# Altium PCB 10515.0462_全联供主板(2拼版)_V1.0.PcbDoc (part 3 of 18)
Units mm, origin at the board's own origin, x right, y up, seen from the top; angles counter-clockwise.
Board outline 282 x 198 mm, 2 copper layers (Top Layer, Bottom Layer); 716 components, 0 nets, 2364 pads, 1800 vias.
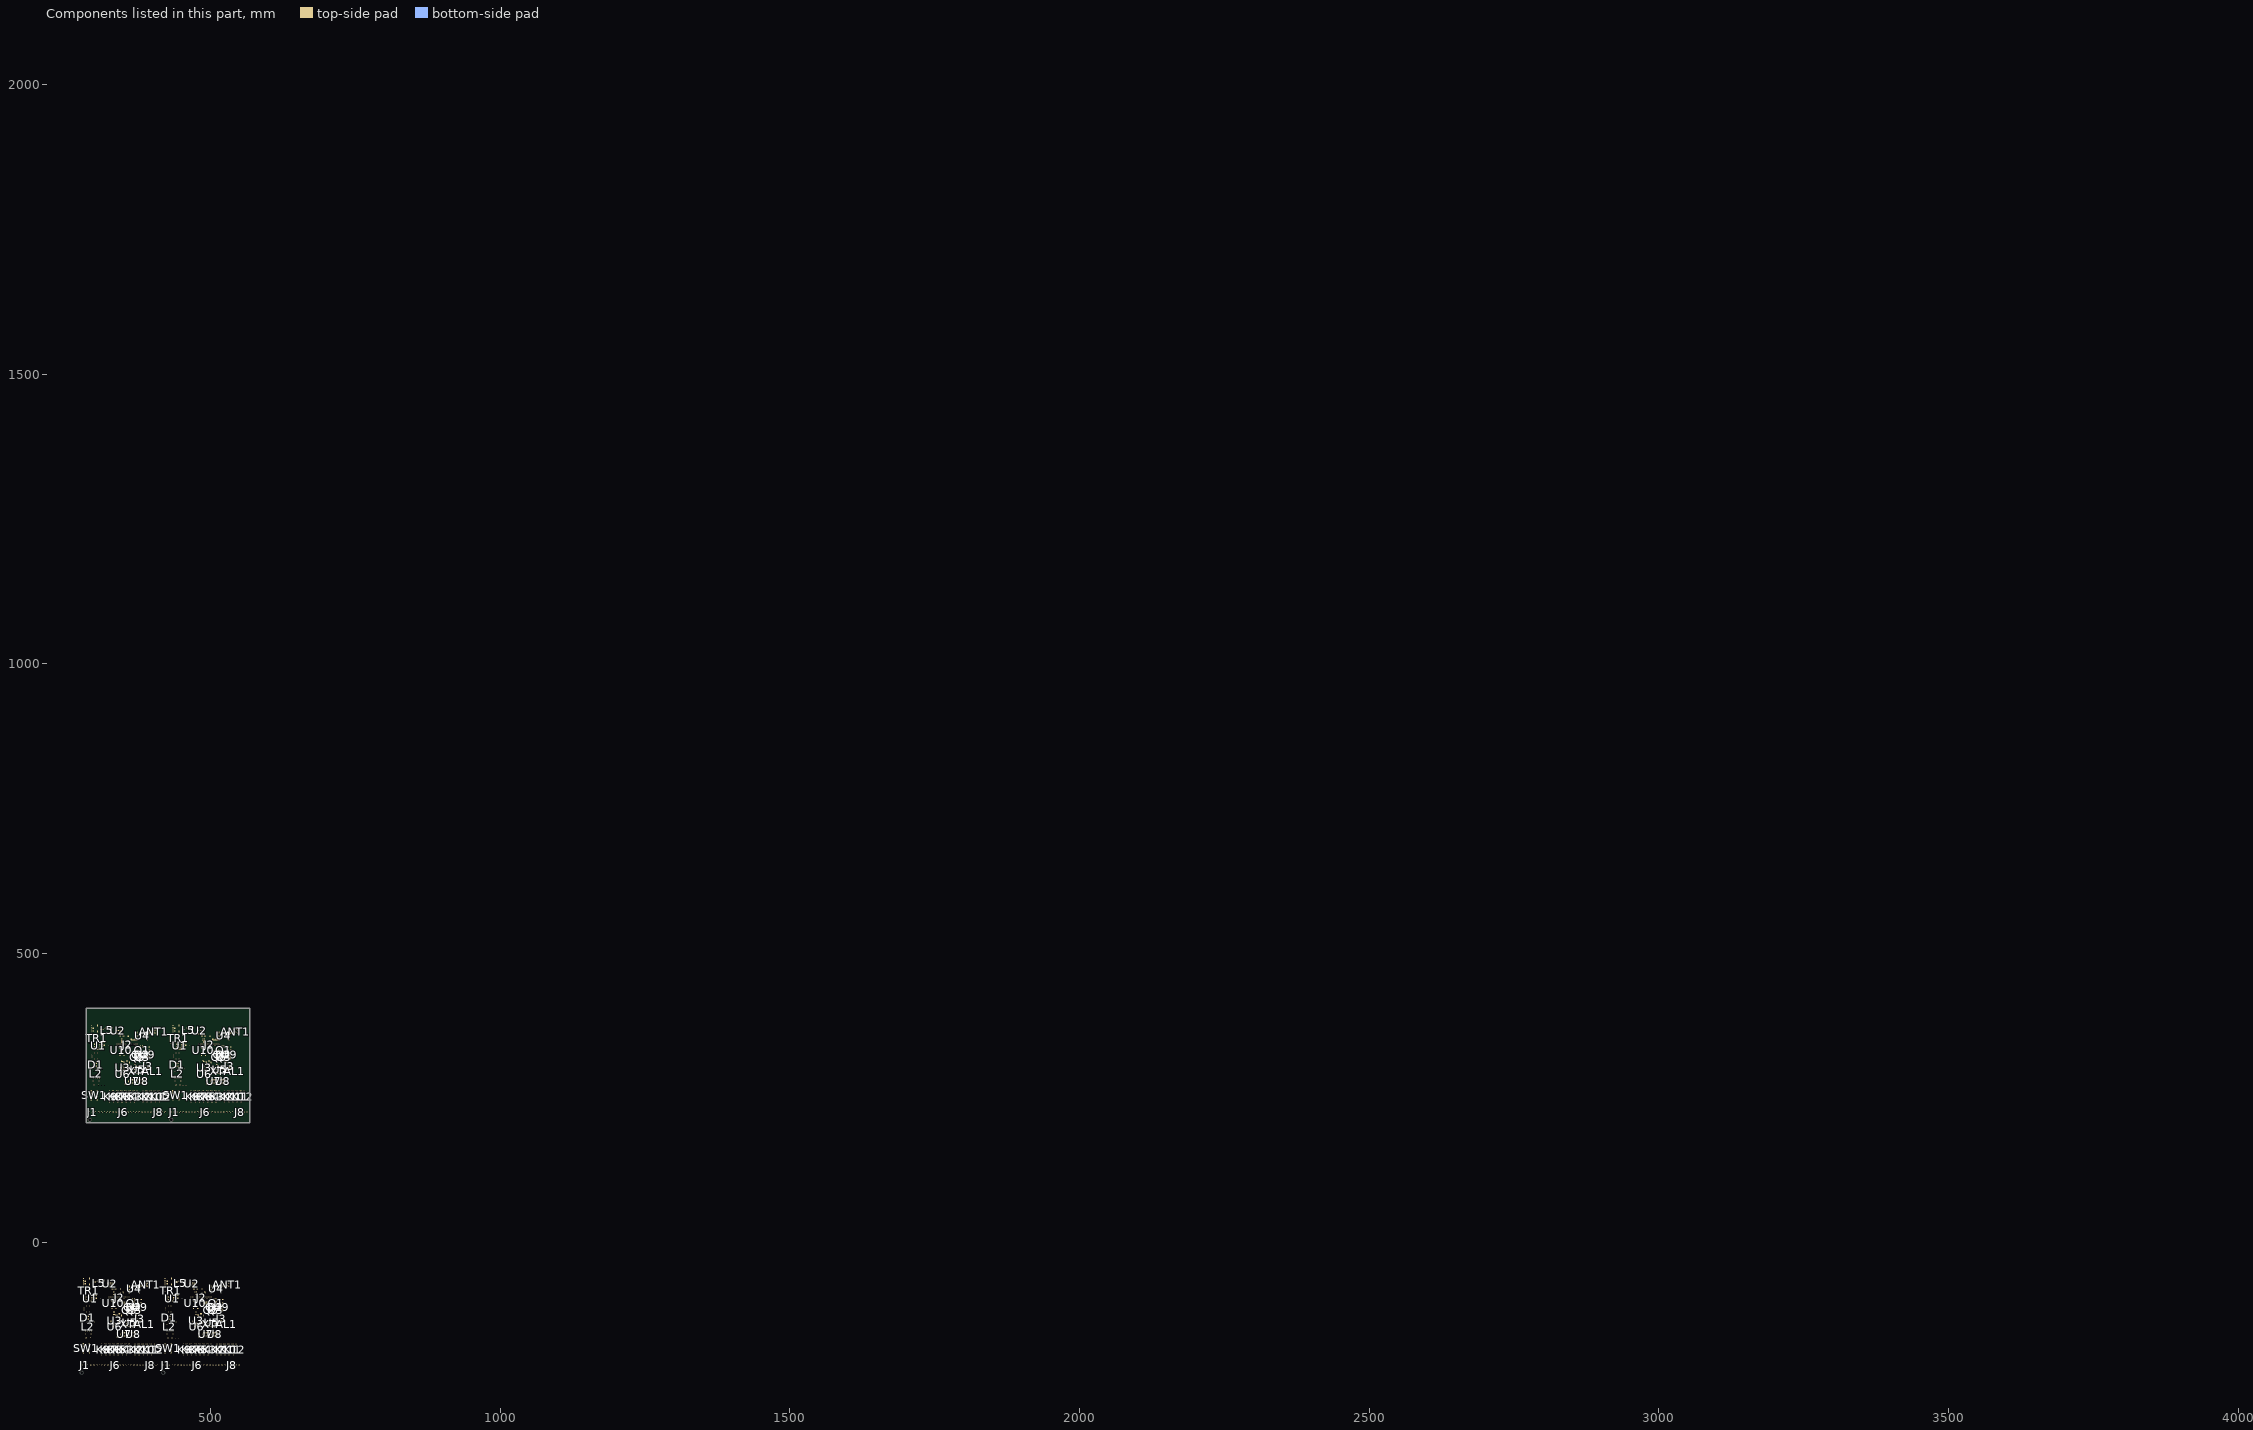
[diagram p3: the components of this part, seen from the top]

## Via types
v1: diameter 0.7, hole 0.4, Top Layer to Bottom Layer, tented both sides, 1800 vias

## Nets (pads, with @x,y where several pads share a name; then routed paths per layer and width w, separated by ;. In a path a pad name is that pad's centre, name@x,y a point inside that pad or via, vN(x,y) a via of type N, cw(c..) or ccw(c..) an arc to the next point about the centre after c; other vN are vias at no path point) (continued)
copper on no net: (continued)
  Top Layer w0.2: 323.371,-67.652 323.436,-67.652 ; 323.712,-72.355 ccw(c323.616,-72.151) 323.841,-72.151 ; 323.801,-72.683 cw(c324.172,-72.444) 323.86,-72.132 ; 323.841,-72.632 323.841,-72.151 ; 323.969,-72.575 cw(c324.386,-72.307) 324.036,-71.957 ; 323.971,-72.355 cw(c324.066,-72.151) 323.841,-72.151 ; 324.137,-72.467 cw(c324.6,-72.17) 324.211,-71.781 ; 324.458,-70.292 325.105,-70.292 325.481,-70.668 325.481,-71.4 325.1,-71.781 324.211,-71.781 ; 324.458,-68.992 325.095,-68.992 ; 324.858,-70.392 cw(c324.858,-71.23) 325.451,-70.638 ; 324.858,-70.192 cw(c324.858,-70.547) 325.109,-70.296 ; 324.891,-68.898 ccw(c325.015,-68.549) 325.276,-68.811 ; 324.91,-70.378 cw(c325.045,-70.599) 325.229,-70.416 ; 324.929,-70.363 cw(c325.099,-70.534) 325.099,-70.292 cw(c325.099,-70.051) 324.929,-70.222 ; 324.93,-69.062 cw(c325.095,-69.223) 325.095,-68.992 ; 324.93,-68.922 ccw(c325.095,-68.762) 325.095,-68.992 ; 325.06,-67.869 cw(c324.537,-68.392) 325.276,-68.392 cw(c326.016,-68.392) 325.493,-67.869 ; 325.276,-67.652 325.276,-68.811 ; v1@326.024,-70.292 327.204,-70.292 ; v1@326.166,-70.434 cw(c326.508,-70.776) 326.508,-70.292 ; v1@326.166,-70.08 ccw(c326.678,-69.568) 326.678,-70.292 ; 326.239,-68.483 ccw(c325.408,-67.652) 326.583,-67.652 ; 326.58,-68.142 ccw(c326.09,-67.652) 326.783,-67.652 ; 326.674,-68.048 cw(c326.889,-68.263) 326.889,-67.959 ; 326.733,-70.363 ccw(c326.563,-70.534) 326.563,-70.292 ccw(c326.563,-70.051) 326.733,-70.222 ; 326.733,-69.713 ccw(c326.563,-69.884) 326.563,-69.642 ccw(c326.563,-69.401) 326.733,-69.572 ; 326.927,-67.652 326.927,-67.795 326.116,-68.606 326.116,-69.368 326.39,-69.642 327.204,-69.642 328.503,-69.642 329.519,-70.658 ; 327.243,-136.468 327.274,-136.499 ; 327.675,-69.713 cw(c327.845,-69.884) 327.845,-69.642 cw(c327.845,-69.401) 327.675,-69.572 ; 328.786,-134.848 328.817,-134.848 328.892,-134.923 ; 328.817,-136.499 329.123,-136.193 ; 328.974,-70.112 cw(c328.367,-70.718) 329.225,-70.718 ; 329.091,-70.23 ccw(c329.531,-69.79) 329.531,-70.412 ; 329.277,-68.852 329.412,-68.987 329.531,-69.106 ; 337,368.943 337.065,368.943 ; 337.34,364.241 ccw(c337.245,364.445) 337.47,364.445 ; 337.43,363.913 cw(c337.801,364.151) 337.489,364.463 ; 337.46,-146.854 342.91,-146.854 343.314,-146.449 343.314,-140.308 343.601,-140.021 349.899,-140.021 ; 337.46,-145.584 342.402,-145.584 342.914,-145.071 342.914,-142.393 ; 337.47,363.963 337.47,364.445 ; 337.598,364.021 cw(c338.015,364.289) 337.664,364.639 ; 337.6,364.241 cw(c337.695,364.445) 337.47,364.445 ; 337.766,364.129 cw(c338.228,364.426) 337.84,364.814 ; 338.087,366.303 338.734,366.303 339.11,365.927 339.11,365.195 338.729,364.814 337.84,364.814 337.47,364.445 ; 338.087,367.603 338.724,367.603 ; 338.481,-91.369 338.481,-91.42 ; 338.487,366.203 cw(c338.487,365.365) 339.079,365.958 ; 338.487,366.403 cw(c338.487,366.048) 338.738,366.299 ; 338.52,367.698 ccw(c338.643,368.047) 338.905,367.785 ; 338.539,366.218 cw(c338.674,365.996) 338.857,366.18 ; 338.557,366.233 cw(c338.728,366.062) 338.728,366.303 cw(c338.728,366.545) 338.557,366.374 ; 338.558,367.534 cw(c338.724,367.373) 338.724,367.603 ; 338.558,367.673 ccw(c338.724,367.834) 338.724,367.603 ; 338.57,-146.998 cw(c338.919,-147.348) 338.919,-146.854 cw(c338.919,-146.359) 338.57,-146.709 ; 338.57,-145.728 cw(c338.919,-146.078) 338.919,-145.584 cw(c338.919,-145.089) 338.57,-145.439 ; 338.689,368.727 cw(c338.166,368.204) 338.905,368.204 cw(c339.645,368.204) 339.122,368.727 ; 338.905,368.943 338.905,367.785 ; v1@339.075,-108.463 ccw(c338.621,-108.425) 338.943,-108.103 ; 339.128,-93.967 cw(c339.738,-94.576) 339.805,-93.717 ; v1@339.303,-108.235 cw(c339.265,-107.781) 338.943,-108.103 ; 339.31,-93.785 ccw(c339.043,-93.517) 339.421,-93.517 ; v1(339.324,-108.484) 338.943,-108.103 ; 339.538,-96.34 cw(c338.252,-97.627) 340.071,-97.627 ; v1@339.653,366.303 340.833,366.303 ; 339.68,-96.199 cw(c338.734,-97.144) 340.071,-97.144 ; v1@339.795,366.162 cw(c340.136,365.82) 340.136,366.303 ; v1@339.795,366.515 ccw(c340.306,367.027) 340.306,366.303 ; 339.821,-96.057 cw(c339.217,-96.661) 340.071,-96.661 ; 339.821,-95.795 340.071,-96.046 340.071,-108.469 340.428,-108.825 351.314,-108.825 351.903,-109.414 351.903,-126.264 351.914,-126.264 352.278,-126.629 357.609,-126.629 358.272,-127.291 358.272,-131.621 ; 339.821,-93.255 339.821,-93.274 338.943,-94.152 338.943,-108.103 ; 339.867,368.112 ccw(c339.036,368.943) 340.212,368.943 ; 339.918,-134.923 339.993,-134.848 ; 340.209,368.454 ccw(c339.719,368.943) 340.412,368.943 ; 340.303,368.548 cw(c340.518,368.333) 340.518,368.637 ; 340.362,366.233 ccw(c340.191,366.062) 340.191,366.303 ccw(c340.191,366.545) 340.362,366.374 ; 340.362,366.883 ccw(c340.191,366.712) 340.191,366.953 ccw(c340.191,367.195) 340.362,367.024 ; v1@340.544,-107.545 ccw(c340.118,-107.118) 340.721,-107.118 ccw(c341.325,-107.118) v1@340.898,-107.545 ; 340.556,368.943 340.556,368.801 339.745,367.989 339.745,367.227 340.019,366.953 340.833,366.953 342.132,366.953 343.148,365.938 ; v1(340.721,-110.389) 340.721,-110.77 ; v1(340.721,-107.722) 340.721,-90.958 341.337,-90.342 374.865,-90.342 375.538,-89.669 375.538,-84.462 375.87,-84.13 ; 340.872,300.128 340.903,300.097 ; 341.303,366.883 cw(c341.474,366.712) 341.474,366.953 cw(c341.474,367.195) 341.303,367.024 ; v1@341.36,-107.214 ccw(c340.757,-107.214) 341.183,-106.787 ccw(c341.61,-106.36) v1@341.61,-106.964 ; v1(341.61,-107.214) 341.121,-106.725 341.121,-92.101 341.121,-91.339 341.718,-90.742 375.354,-90.742 376.027,-90.069 376.027,-86.64 376.537,-86.13 377.003,-86.13 ; v1(341.737,-110.389) 341.864,-110.262 350.269,-110.262 350.703,-110.697 350.703,-132.646 350.701,-132.648 350.701,-133.85 350.703,-133.852 350.703,-134.573 351.152,-135.021 354.372,-135.021 ; v1@341.772,-110.424 cw(c342.164,-110.816) 342.164,-110.262 ; v1@341.914,-110.566 cw(c342.647,-111.299) 342.647,-110.262 ; 342.078,-96.34 cw(c341.395,-97.023) 342.361,-97.023 cw(c343.327,-97.023) 342.644,-96.34 ; v1@342.122,-91.593 cw(c341.519,-91.593) 341.945,-92.02 cw(c342.372,-92.447) v1@342.372,-91.843 ; v1@342.195,-107.545 ccw(c341.769,-107.118) 342.372,-107.118 ccw(c342.976,-107.118) v1@342.549,-107.545 ; 342.361,-95.795 342.361,-106.314 343.022,-106.975 343.022,-107.864 343.584,-108.425 351.966,-108.425 352.303,-108.763 352.303,-125.756 352.684,-126.137 357.999,-126.137 358.772,-126.91 358.772,-131.621 ; 342.361,-93.255 343.161,-94.055 343.161,-106.467 343.422,-106.728 343.422,-107.698 343.749,-108.025 352.131,-108.025 352.703,-108.597 352.703,-125.292 353.04,-125.629 358.499,-125.629 359.272,-126.402 359.272,-131.621 ; v1(342.372,-107.722) 342.372,-106.96 341.521,-106.109 341.521,-92.444 v1(342.372,-91.593) ; 342.395,-93.715 cw(c342.515,-94.417) 343.019,-93.913 ; 342.415,301.748 342.446,301.748 342.52,301.673 ; 342.446,300.097 342.752,300.403 ; 342.602,366.483 cw(c341.996,365.877) 342.853,365.877 ; 342.72,366.366 ccw(c343.16,366.806) 343.16,366.183 ; v1@342.753,-112.036 cw(c342.753,-112.64) 343.18,-112.213 cw(c343.607,-111.786) v1@343.003,-111.786 ; v1(342.753,-111.786) 343.403,-112.436 344.658,-112.436 344.908,-112.186 349.249,-112.186 349.503,-112.44 349.503,-132.149 349.501,-132.151 349.501,-134.347 349.503,-134.349 349.503,-135.139 350.886,-136.521 354.372,-136.521 ; 342.761,-93.517 ccw(c343.094,-93.517) 342.859,-93.753 ; 342.906,367.744 343.041,367.608 343.16,367.49 ; 342.914,-141.134 342.914,-142.393 ; v1@343.465,-92.278 cw(c343.039,-92.705) 343.642,-92.705 cw(c344.246,-92.705) v1@343.819,-92.278 ; v1(343.642,-92.101) 343.642,-106.383 344.101,-106.842 ; v1@343.973,-107.164 ccw(c343.665,-106.856) 344.101,-106.856 ; v1(344.023,-111.786) 349.738,-111.786 349.903,-111.951 349.903,-132.315 349.901,-132.317 349.901,-134.181 349.903,-134.183 349.903,-134.973 350.951,-136.021 354.372,-136.021 ; v1(344.15,-107.341) 344.101,-107.292 344.101,-106.842 ; v1@344.2,-111.963 cw(c344.627,-112.39) 344.627,-111.786 cw(c344.627,-111.182) v1@344.2,-111.609 ; 344.212,-93.944 cw(c344.778,-94.51) 344.876,-93.716 ; v1@344.268,-107.121 cw(c344.417,-106.842) 344.101,-106.842 ; 344.403,-93.753 ccw(c344.168,-93.517) 344.501,-93.517 ; 344.617,-136.435 344.642,-136.461 ; 344.618,-96.34 cw(c343.935,-97.023) 344.901,-97.023 cw(c345.867,-97.023) 345.184,-96.34 ; 344.901,-95.795 344.901,-106.441 345.686,-107.225 353.179,-107.225 353.503,-107.55 353.503,-124.403 353.929,-124.829 359.461,-124.829 360.272,-125.64 360.272,-131.621 ; 344.901,-93.255 344.054,-94.103 344.054,-106.228 345.451,-107.625 352.69,-107.625 353.103,-108.039 353.103,-124.911 353.421,-125.229 358.98,-125.229 359.772,-126.021 359.772,-131.621 ; v1@345.293,-112.929 v1(345.547,-112.929) 348.468,-112.929 349.103,-113.564 349.103,-131.984 349.101,-131.986 349.101,-134.512 349.103,-134.514 349.103,-135.386 350.739,-137.021 354.372,-137.021 ; v1@345.678,-106.452 ccw(c345.075,-106.452) 345.501,-106.025 ccw(c345.928,-105.598) v1@345.928,-106.202 ; v1@345.724,-113.106 cw(c346.151,-113.533) 346.151,-112.929 cw(c346.151,-112.325) v1@345.724,-112.752 ; v1@345.751,-92.278 cw(c345.325,-92.705) 345.928,-92.705 cw(c346.532,-92.705) v1@346.105,-92.278 ; v1(345.928,-106.452) 345.42,-105.944 345.42,-97.17 345.928,-96.662 v1(345.928,-92.101) ; 346.102,-136.461 346.127,-136.461 ; 346.187,-138.115 cw(c345.504,-138.798) 346.47,-138.798 cw(c347.436,-138.798) 346.753,-138.115 ; 346.47,-137.832 346.47,-138.848 346.654,-139.032 354.361,-139.032 354.372,-139.021 ; 347.436,-153.924 ccw(c347.009,-153.497) 347.613,-153.497 ccw(c348.217,-153.497) 347.79,-153.924 ; 347.507,-136.097 347.833,-136.424 349.507,-136.424 350.604,-137.521 354.372,-137.521 ; 347.613,-154.85 347.613,-150.278 348.267,-149.624 356.757,-149.624 357.272,-149.109 357.272,-143.921 ; 347.897,-105.537 cw(c347.374,-106.06) 348.114,-106.06 cw(c348.854,-106.06) 348.331,-105.537 ; 347.994,-137.832 347.994,-138.285 348.341,-138.632 353.118,-138.632 353.229,-138.521 354.372,-138.521 ; 348.058,-136.652 cw(c348.609,-137.203) 348.609,-136.424 ; 348.058,-136.219 ccw(c348.554,-135.723) 348.554,-136.424 ; 348.114,-105.32 348.114,-106.471 348.468,-106.825 353.515,-106.825 353.903,-107.214 353.903,-124.105 354.227,-124.429 360.069,-124.429 360.772,-125.132 360.772,-131.621 ; 348.114,-103.669 v1@348.756,-103.669 ; 348.399,-103.85 cw(c348.756,-104.111) v1@348.756,-103.669 ; 348.399,-103.489 ccw(c348.756,-103.228) v1@348.756,-103.669 ; 348.706,-153.924 ccw(c348.279,-153.497) 348.883,-153.497 ccw(c349.487,-153.497) 349.06,-153.924 ; v1@348.706,-103.846 ccw(c348.279,-104.273) 348.279,-103.669 ccw(c348.279,-103.066) v1@348.706,-103.493 ; 348.883,-154.85 348.883,-150.786 349.645,-150.024 357.138,-150.024 357.772,-149.39 357.772,-143.921 ; 349.682,-141.238 ccw(c349.159,-140.715) 349.899,-140.715 ccw(c350.639,-140.715) 350.116,-141.238 ; 349.707,-138.021 354.372,-138.021 ; 349.899,-141.492 349.899,-140.021 ; 349.976,-153.924 ccw(c349.549,-153.497) 350.153,-153.497 ccw(c350.757,-153.497) 350.33,-153.924 ; 350.153,-154.85 350.153,-151.167 350.845,-150.475 357.703,-150.475 358.272,-149.906 358.272,-143.921 ; 351.089,289.742 356.539,289.742 356.943,290.146 356.943,296.287 357.229,296.574 363.528,296.574 ; 351.089,291.012 356.031,291.012 356.543,291.524 356.543,294.202 ; 351.246,-153.924 ccw(c350.819,-153.497) 351.423,-153.497 ccw(c352.027,-153.497) 351.6,-153.924 ; 351.423,-154.85 351.423,-151.421 351.969,-150.875 358.192,-150.875 358.772,-150.295 358.772,-143.921 ; 351.46,-105.537 cw(c350.937,-106.06) 351.677,-106.06 cw(c352.417,-106.06) 351.894,-105.537 ; 351.632,-101.941 v1@352.262,-101.941 ; 351.657,-141.49 351.727,-141.49 ; 351.677,-105.32 351.677,-106.078 352.024,-106.425 354.03,-106.425 354.303,-106.699 354.303,-123.724 354.303,-123.768 354.564,-124.029 360.55,-124.029 361.272,-124.751 361.272,-131.621 ; 351.677,-103.669 v1(352.439,-103.669) ; 351.727,-143.141 352.464,-143.141 ; 351.92,-102.118 cw(c352.262,-102.36) v1@352.262,-101.941 ; 351.92,-101.765 ccw(c352.262,-101.523) v1@352.262,-101.941 ; 351.935,-103.883 cw(c352.439,-104.371) v1@352.439,-103.669 ; 351.935,-103.456 ccw(c352.439,-102.968) v1@352.439,-103.669 ; 351.944,-143.357 cw(c352.464,-143.875) 352.464,-143.141 ; 351.944,-142.925 ccw(c352.464,-142.407) 352.464,-143.141 ; 352.11,345.226 352.11,345.175 ; 352.199,289.597 cw(c352.548,289.247) 352.548,289.742 cw(c352.548,290.236) 352.199,289.887 ; 352.199,290.867 cw(c352.548,290.517) 352.548,291.012 cw(c352.548,291.506) 352.199,291.157 ; v1@352.212,-102.118 ccw(c351.785,-102.545) 351.785,-101.941 ccw(c351.785,-101.338) v1@352.212,-101.765 ; v1@352.262,-103.846 ccw(c351.835,-104.273) 351.835,-103.669 ccw(c351.835,-103.066) v1@352.262,-103.493 ; 352.516,-153.924 ccw(c352.089,-153.497) 352.693,-153.497 ccw(c353.297,-153.497) 352.87,-153.924 ; 352.521,-93.917 cw(c352.521,-95.516) 353.651,-94.386 cw(c354.781,-93.255) 353.183,-93.255 ; 352.521,-93.717 cw(c352.521,-94.833) 353.31,-94.044 cw(c354.098,-93.255) 352.983,-93.255 ; 352.521,-93.255 353.802,-94.537 353.802,-98.324 354.075,-98.597 357.485,-98.597 357.823,-98.935 357.823,-99.805 358.12,-100.102 371.328,-100.102 371.709,-100.483 371.709,-113.564 372.217,-114.072 ; 352.693,-154.85 352.693,-151.929 353.347,-151.275 358.554,-151.275 359.272,-150.557 359.272,-143.921 ; v1@352.704,328.132 ccw(c352.25,328.17) 352.572,328.492 ccw(c352.894,328.815) v1@352.932,328.361 ; 352.757,342.629 cw(c353.367,342.019) 353.434,342.879 ; v1@352.786,-81.56 355.834,-81.56 356.45,-81.56 356.704,-81.306 356.704,-72.784 357.358,-72.13 359.303,-72.13 ; v1@352.913,-141.021 354.372,-141.021 ; 352.939,342.811 ccw(c352.672,343.078) 353.05,343.078 ; v1(352.953,328.111) 352.572,328.492 352.572,342.443 353.45,343.321 353.45,343.34 ; 353.167,340.255 cw(c351.88,338.969) 353.7,338.969 ; v1(353.294,-82.322) 353.548,-82.068 355.58,-82.068 356.85,-82.068 357.104,-81.814 357.104,-81.179 357.104,-74.575 357.549,-74.13 359.303,-74.13 ; 353.308,340.397 cw(c352.363,339.451) 353.7,339.451 ; 353.389,-141.663 cw(c353.707,-141.981) 353.707,-141.531 ; 353.443,-141.61 cw(c353.646,-141.813) 353.705,-141.531 ; 353.45,340.538 cw(c352.846,339.934) 353.7,339.934 ; 353.45,340.8 353.7,340.55 353.7,328.126 354.056,327.77 364.943,327.77 365.532,327.181 365.532,310.331 365.542,310.331 365.907,309.967 371.238,309.967 371.901,309.304 371.901,304.974 ; 353.547,301.673 353.622,301.748 ; 353.786,-153.924 ccw(c353.359,-153.497) 353.963,-153.497 ccw(c354.567,-153.497) 354.14,-153.924 ; v1@353.929,-82.957 356.469,-82.957 357.358,-82.957 357.612,-82.703 357.612,-80.384 357.866,-80.13 ; 353.963,-154.85 353.963,-152.183 354.471,-151.675 359.043,-151.675 359.772,-150.946 359.772,-143.921 ; v1@354.106,-83.134 cw(c354.533,-83.561) 354.533,-82.957 cw(c354.533,-82.353) v1@354.106,-82.78 ; v1@354.173,329.05 ccw(c353.746,329.477) 354.35,329.477 ccw(c354.953,329.477) v1@354.527,329.05 ; v1(354.35,326.206) 354.35,325.825 ; v1(354.35,328.873) 354.35,345.637 354.966,346.253 388.494,346.253 389.167,346.926 389.167,352.133 389.499,352.465 ; 354.372,-141.521 353.531,-141.521 352.82,-142.232 352.82,-142.785 352.464,-143.141 ; 354.372,-140.521 363.768,-140.521 364.055,-140.234 364.055,-133.41 364.993,-132.472 365.979,-132.472 v1(366.629,-133.122) ; 354.372,-140.021 349.899,-140.021 ; 354.372,-139.521 343.212,-139.521 342.914,-139.819 342.914,-142.393 ; 354.372,-135.521 351.017,-135.521 350.303,-134.808 350.303,-134.017 350.301,-134.015 350.301,-132.483 350.303,-132.481 350.303,-111.211 350.117,-111.024 342.021,-111.024 342.006,-111.039 340.99,-111.039 340.721,-110.77 ; 354.372,-134.521 351.414,-134.521 351.103,-134.211 351.103,-133.686 351.101,-133.684 351.101,-132.814 351.103,-132.812 351.103,-110.322 350.407,-109.625 338.63,-109.625 338.081,-109.077 338.081,-89.915 338.562,-89.434 374.122,-89.434 374.63,-88.926 374.63,-80.798 375.298,-80.13 377.003,-80.13 ; 354.372,-134.021 351.781,-134.021 351.503,-133.744 351.503,-133.52 351.501,-133.518 351.501,-132.98 351.503,-132.978 351.503,-109.814 350.915,-109.225 338.796,-109.225 338.481,-108.911 338.481,-91.42 ; 354.593,-96.264 cw(c353.463,-97.394) 355.061,-97.394 cw(c356.659,-97.394) 355.529,-96.264 ; 354.734,-96.122 cw(c353.946,-96.911) 355.061,-96.911 cw(c356.176,-96.911) 355.388,-96.122 ; 354.882,-105.537 cw(c354.359,-106.06) 355.099,-106.06 cw(c355.839,-106.06) 355.316,-105.537 ; 354.915,-129.971 cw(c354.392,-130.494) 355.131,-130.494 cw(c355.871,-130.494) 355.348,-129.971 ; v1@354.989,329.381 ccw(c354.385,329.381) 354.812,329.808 ccw(c355.239,330.235) v1@355.239,329.631 ; 355.056,-153.924 ccw(c354.629,-153.497) 355.233,-153.497 ccw(c355.837,-153.497) 355.41,-153.924 ; 355.061,-95.795 355.061,-97.932 355.326,-98.197 357.745,-98.197 358.227,-98.679 358.227,-99.428 358.501,-99.702 371.69,-99.702 372.109,-100.121 372.109,-100.864 372.109,-113.202 372.344,-113.437 373.233,-113.437 373.614,-113.818 ; 355.061,-93.917 cw(c355.061,-95.516) 356.191,-94.386 cw(c357.321,-93.255) 355.723,-93.255 ; 355.061,-93.717 cw(c355.061,-94.833) 355.85,-94.044 cw(c356.638,-93.255) 355.523,-93.255 ; 355.061,-93.255 356.215,-94.41 356.215,-97.543 356.469,-97.797 357.911,-97.797 358.311,-98.197 364.871,-98.197 ; 355.099,-105.32 355.099,-106.298 354.703,-106.694 354.703,-123.216 354.703,-123.26 355.072,-123.629 360.819,-123.629 361.772,-124.582 361.772,-131.621 ; 355.099,-103.669 355.443,-103.669 355.106,-103.669 ; 355.131,-129.754 355.131,-130.514 355.453,-130.836 356.596,-130.836 ; 355.233,-154.85 355.233,-152.818 355.868,-152.183 359.297,-152.183 360.272,-151.208 360.272,-143.921 ; v1(355.239,329.381) 354.75,329.87 354.75,344.494 354.75,345.256 355.347,345.853 388.983,345.853 389.656,346.526 389.656,349.955 390.166,350.465 390.632,350.465 ; 355.324,-114.27 ccw(c354.778,-113.724) 355.551,-113.724 ; 355.334,-112.96 cw(c354.811,-113.483) 355.551,-113.483 cw(c356.29,-113.483) 355.767,-112.96 ; v1(355.366,326.206) 355.493,326.333 363.897,326.333 364.332,325.899 364.332,303.949 364.33,303.947 364.33,302.746 364.332,302.744 364.332,302.023 364.781,301.574 368.001,301.574 ; v1@355.401,326.171 cw(c355.793,325.779) 355.793,326.333 ; v1@355.543,326.03 cw(c356.276,325.296) 356.276,326.333 ; 355.551,-114.439 355.551,-112.743 ; 355.551,-113.77 ccw(c356.258,-113.77) 355.758,-114.27 ; 355.707,340.255 cw(c355.024,339.572) 355.99,339.572 cw(c356.955,339.572) 356.273,340.255 ; v1@355.751,345.002 cw(c355.147,345.002) 355.574,344.576 cw(c356.001,344.149) v1@356.001,344.752 ; v1@355.824,329.05 ccw(c355.397,329.477) 356.001,329.477 ccw(c356.604,329.477) v1@356.178,329.05 ; 355.99,340.8 355.99,330.282 356.651,329.62 356.651,328.731 357.212,328.17 365.594,328.17 365.932,327.832 365.932,310.839 366.313,310.458 371.627,310.458 372.401,309.685 372.401,304.974 ; 355.99,343.34 356.79,342.54 356.79,330.128 357.051,329.867 357.051,328.897 357.378,328.57 365.76,328.57 366.332,327.998 366.332,311.303 366.669,310.966 372.127,310.966 372.901,310.193 372.901,304.974 ; v1(356.001,328.873) 356.001,329.635 355.15,330.486 355.15,344.151 v1(356.001,345.002) ; 356.024,342.881 cw(c356.144,342.179) 356.647,342.682 ; v1@356.382,324.559 cw(c356.382,323.956) 356.809,324.383 cw(c357.235,324.809) v1@356.632,324.809 ; v1(356.382,324.809) 357.032,324.159 358.287,324.159 358.537,324.409 362.878,324.409 363.132,324.155 363.132,304.446 363.13,304.444 363.13,302.249 363.132,302.247 363.132,301.457 364.514,300.074 368.001,300.074 ; 356.39,343.078 ccw(c356.723,343.078) 356.487,342.842 ; 356.457,-130.836 cw(c356.457,-131.271) 356.765,-130.963 ; 356.543,295.461 356.543,294.202 ; 356.66,-130.9 ccw(c356.772,-130.788) 356.772,-130.946 ; 356.762,-130.959 ccw(c356.596,-131.01) 356.596,-130.836 ; 356.772,-143.921 356.772,-141.963 357.104,-141.631 363.835,-141.631 364.455,-141.011 364.455,-133.645 364.978,-133.122 v1(365.613,-133.122) ; 356.772,-131.621 356.772,-131.012 356.596,-130.836 ; 356.782,-129.754 357.272,-130.244 357.272,-131.621 ; 356.833,-130.061 cw(c356.855,-130.623) 357.253,-130.225 cw(c357.587,-129.891) 357.122,-129.808 ; 356.985,-116.474 cw(c356.462,-116.997) 357.202,-116.997 cw(c357.941,-116.997) 357.418,-116.474 ; v1@357.094,344.318 cw(c356.667,343.891) 357.271,343.891 cw(c357.874,343.891) v1@357.448,344.318 ; 357.202,-116.257 357.202,-120.243 357.202,-122.818 357.599,-123.216 361.93,-123.216 362.272,-123.558 362.272,-131.621 ; v1(357.271,344.494) 357.271,330.213 357.73,329.754 ; 357.601,-95.795 357.601,-96.916 357.866,-97.181 361.422,-97.181 362.946,-95.657 364.871,-95.657 ; 357.601,-93.917 cw(c357.601,-95.516) 358.731,-94.386 cw(c359.861,-93.255) 358.263,-93.255 ; 357.601,-93.717 cw(c357.601,-94.833) 358.39,-94.044 cw(c359.178,-93.255) 358.063,-93.255 ; 357.601,-93.255 358.86,-94.514 360.857,-94.514 361.619,-93.752 383.52,-93.752 384.047,-94.279 384.047,-144.533 383.412,-145.168 370.224,-145.168 369.692,-144.636 369.692,-141.115 369.098,-140.521 366.672,-140.521 ; v1@357.602,329.431 ccw(c357.294,329.739) 357.73,329.739 ; v1(357.652,324.809) 363.367,324.809 363.532,324.644 363.532,304.28 363.53,304.278 363.53,302.415 363.532,302.413 363.532,301.622 364.58,300.574 368.001,300.574 ; v1(357.779,329.254) 357.73,329.304 357.73,329.754 ; v1@357.829,324.633 cw(c358.255,324.206) 358.255,324.809 cw(c358.255,325.413) v1@357.829,324.986 ; 357.841,342.651 cw(c358.407,342.085) 358.505,342.88 ; v1@357.897,329.475 cw(c358.046,329.754) 357.73,329.754 ; 358.032,342.842 ccw(c357.797,343.078) 358.13,343.078 ; 358.245,300.16 358.271,300.135 ; 358.247,340.255 cw(c357.564,339.572) 358.53,339.572 cw(c359.495,339.572) 358.813,340.255 ; 358.53,340.8 358.53,330.155 359.314,329.37 366.807,329.37 367.132,329.045 367.132,312.192 367.558,311.766 373.089,311.766 373.901,310.955 373.901,304.974 ; 358.53,343.34 357.682,342.493 357.682,330.367 359.079,328.97 366.318,328.97 366.732,328.556 366.732,311.684 367.05,311.366 372.608,311.366 373.401,310.574 373.401,304.974 ; 358.57,-80.413 ccw(c357.887,-81.096) 357.887,-80.13 ; 358.57,-79.847 cw(c357.887,-79.164) 357.887,-80.13 ; 358.57,-74.413 ccw(c357.887,-75.096) 357.887,-74.13 ccw(c357.887,-73.164) 358.57,-73.847 ; 358.57,-72.413 ccw(c357.887,-73.096) 357.887,-72.13 ccw(c357.887,-71.164) 358.57,-71.847 ; 358.89,-119.126 cw(c358.367,-119.649) 359.107,-119.649 cw(c359.846,-119.649) 359.323,-119.126 ; v1@358.922,323.666 v1(359.176,323.666) 362.097,323.666 362.732,323.031 362.732,304.612 362.73,304.61 362.73,302.083 362.732,302.081 362.732,301.21 364.368,299.574 368.001,299.574 ; 359.107,-118.909 359.107,-121.154 359.263,-121.311 366.629,-121.311 366.968,-121.65 366.968,-131.177 366.524,-131.621 364.272,-131.621 ; 359.303,-80.13 357.887,-80.13 ; v1@359.307,330.143 ccw(c358.703,330.143) 359.13,330.57 ccw(c359.557,330.997) v1@359.557,330.393 ; v1@359.353,323.49 cw(c359.779,323.063) 359.779,323.666 cw(c359.779,324.27) v1@359.353,323.843 ; v1@359.38,344.318 cw(c358.953,343.891) 359.557,343.891 cw(c360.16,343.891) v1@359.734,344.318 ; v1(359.557,330.143) 359.049,330.651 359.049,339.426 359.557,339.934 v1(359.557,344.494) ; 359.73,300.135 359.756,300.135 ; 359.816,298.48 cw(c359.133,297.797) 360.099,297.797 cw(c361.064,297.797) 360.382,298.48 ; 360.099,298.763 360.099,297.747 360.283,297.563 367.99,297.563 368.001,297.574 ; 360.141,-93.255 384.04,-93.255 384.447,-93.663 384.447,-144.768 383.647,-145.568 370.058,-145.568 369.203,-144.713 369.203,-141.388 368.836,-141.021 366.672,-141.021 ; 360.313,-95.623 360.141,-95.795 361.784,-94.152 383.158,-94.152 383.647,-94.641 383.647,-144.367 383.246,-144.768 370.389,-144.768 370.092,-144.471 370.092,-140.753 369.36,-140.021 366.672,-140.021 ; 360.468,-93.582 cw(c361.256,-94.371) 361.256,-93.255 cw(c361.256,-92.14) 360.468,-92.929 ; 360.609,-93.724 cw(c361.739,-94.854) 361.739,-93.255 cw(c361.739,-91.657) 360.609,-92.787 ; 360.758,-109.765 360.782,-109.79 ; 360.772,-143.921 360.772,-151.649 361.587,-152.464 362.753,-152.464 362.98,-152.691 362.98,-154.85 ; 360.78,-114.423 360.948,-114.591 ; 360.78,-112.803 360.782,-112.801 ; 361.065,282.672 ccw(c360.638,283.099) 361.242,283.099 ccw(c361.845,283.099) 361.419,282.672 ; 361.135,300.498 361.462,300.171 363.135,300.171 364.233,299.074 368.001,299.074 ; 361.242,281.745 361.242,286.317 361.896,286.971 370.386,286.971 370.901,287.486 370.901,292.674 ; 361.272,-143.921 361.272,-151.387 361.949,-152.064 363.877,-152.064 364.25,-152.437 364.25,-154.85 ; 361.526,331.058 cw(c361.003,330.535) 361.743,330.535 cw(c362.483,330.535) 361.96,331.058 ; 361.623,298.763 361.623,298.31 361.97,297.963 366.746,297.963 366.857,298.074 368.001,298.074 ; 361.687,299.943 cw(c362.238,299.393) 362.238,300.171 ; 361.687,300.377 ccw(c362.183,300.872) 362.183,300.171 ; 361.743,331.275 361.743,330.124 362.097,329.77 367.143,329.77 367.532,329.381 367.532,312.49 367.856,312.166 373.697,312.166 374.401,311.463 374.401,304.974 ; 361.743,332.926 v1@362.385,332.926 ; 361.772,-143.921 361.772,-150.998 362.438,-151.664 365.255,-151.664 365.52,-151.929 365.52,-154.85 ; 362.028,332.745 cw(c362.385,332.484) v1@362.385,332.926 ; 362.028,333.107 ccw(c362.385,333.368) v1@362.385,332.926 ; 362.272,-143.921 362.272,-147.357 362.853,-147.938 362.853,-148.31 ; 362.335,282.672 ccw(c361.908,283.099) 362.512,283.099 ccw(c363.115,283.099) 362.689,282.672 ; v1@362.335,332.749 ccw(c361.908,332.323) 361.908,332.926 ccw(c361.908,333.53) v1@362.335,333.103 ; 362.443,-147.528 cw(c361.709,-148.262) 362.747,-148.271 ; v1@362.502,-122.25 cw(c361.851,-122.901) 362.772,-122.901 ; 362.512,281.745 362.512,285.809 363.274,286.571 370.767,286.571 371.401,287.205 371.401,292.674 ; v1@362.644,-122.108 cw(c362.334,-122.418) 362.772,-122.418 ; 362.772,-143.921 362.772,-147.149 363.107,-147.484 363.869,-147.484 364.123,-147.738 364.123,-150.856 364.377,-151.11 366.479,-151.11 366.79,-151.421 366.79,-154.85 ; 362.772,-131.621 v1@362.772,-122.166 ; 362.772,-122.452 cw(c363.058,-122.452) v1@362.856,-122.25 ; 362.772,-116.75 362.772,-116.641 ; 362.78,-147.865 cw(c362.378,-148.268) 362.947,-148.273 ; 362.803,-153.924 ccw(c362.376,-153.497) 362.98,-153.497 ccw(c363.584,-153.497) 363.157,-153.924 ; 363.272,-143.921 363.272,-146.868 363.488,-147.084 364.035,-147.084 364.523,-147.573 364.523,-150.475 364.758,-150.71 367.603,-150.71 368.06,-151.167 368.06,-154.85 ; 363.272,-130.403 cw(c365.139,-130.403) 363.819,-129.082 ; 363.272,-129.92 cw(c364.657,-129.92) 363.678,-128.941 ; 363.272,-129.64 363.272,-131.621 363.272,-128.878 ; 363.272,-129.437 cw(c364.174,-129.437) 363.536,-128.799 ; 363.311,295.358 ccw(c362.788,295.881) 363.528,295.881 ccw(c364.267,295.881) 363.744,295.358 ; 363.336,298.574 368.001,298.574 ; 363.528,295.103 363.528,296.574 ; 363.605,282.672 ccw(c363.178,283.099) 363.782,283.099 ccw(c364.385,283.099) 363.959,282.672 ; 363.764,-145.449 cw(c363.175,-146.037) 364.007,-146.037 ; 363.772,-131.621 363.772,-130.055 363.996,-129.831 365.139,-129.831 365.291,-129.679 365.291,-128.865 ; 363.782,281.745 363.782,285.428 364.474,286.12 371.332,286.12 371.901,286.689 371.901,292.674 ; 363.855,-145.541 ccw(c364.314,-145.083) 364.314,-145.731 ; 364.073,-153.924 ccw(c363.646,-153.497) 364.25,-153.497 ccw(c364.854,-153.497) 364.427,-153.924 ; 364.351,-119.126 cw(c363.828,-119.649) 364.568,-119.649 cw(c365.307,-119.649) 364.784,-119.126 ; 364.352,-146.037 363.772,-145.458 363.772,-143.921 363.772,-142.271 365.105,-140.938 v1(365.105,-139.091) 365.105,-136.297 365.381,-136.021 366.672,-136.021 369.026,-136.021 369.28,-135.767 369.28,-134.937 369.407,-134.937 ; 364.411,-98.657 ccw(c363.301,-99.766) 363.301,-98.197 ccw(c363.301,-96.628) 364.411,-97.737 ; 364.411,-96.117 ccw(c363.301,-97.226) 363.301,-95.657 ccw(c363.301,-94.088) 364.411,-95.197 ; 364.553,-98.515 ccw(c363.784,-99.283) 363.784,-98.197 ccw(c363.784,-97.111) 364.553,-97.879 ; 364.553,-95.975 ccw(c363.784,-96.743) 363.784,-95.657 ccw(c363.784,-94.571) 364.553,-95.339 ; 364.568,-118.909 364.568,-120.646 364.832,-120.911 367.01,-120.911 367.368,-121.269 367.368,-133.641 ; 364.875,282.672 ccw(c364.448,283.099) 365.052,283.099 ccw(c365.655,283.099) 365.229,282.672 ; v1@364.928,-139.268 cw(c364.502,-139.695) 365.105,-139.695 cw(c365.709,-139.695) v1@365.282,-139.268 ; v1@364.928,-138.914 ccw(c364.502,-138.487) 365.105,-138.487 ccw(c365.709,-138.487) v1@365.282,-138.914 ; 365.052,281.745 365.052,285.174 365.598,285.72 371.821,285.72 372.401,286.3 372.401,292.674 ; 365.075,-129.082 cw(c364.552,-129.605) 365.291,-129.605 cw(c366.031,-129.605) 365.508,-129.082 ; 365.089,331.058 cw(c364.566,330.535) 365.306,330.535 cw(c366.045,330.535) 365.522,331.058 ; 365.261,334.654 v1@365.891,334.654 ; 365.286,295.105 365.356,295.105 ; 365.306,331.275 365.306,330.517 365.653,330.17 367.658,330.17 367.932,329.897 367.932,312.871 367.932,312.827 368.193,312.566 374.178,312.566 374.901,311.844 374.901,304.974 ; 365.306,332.926 v1(366.068,332.926) ; 365.343,-153.924 ccw(c364.916,-153.497) 365.52,-153.497 ccw(c366.124,-153.497) 365.697,-153.924 ; 365.356,293.454 366.093,293.454 ; 365.358,-145.313 cw(c364.633,-146.037) 365.658,-146.037 ; v1@365.436,-133.299 ccw(c365.01,-133.726) 365.01,-133.122 ccw(c365.01,-132.518) v1@365.436,-132.945 ; 365.549,334.477 cw(c365.891,334.236) v1@365.891,334.654 ; 365.549,334.831 ccw(c365.891,335.073) v1@365.891,334.654 ; 365.564,332.713 cw(c366.068,332.224) v1(366.068,332.926) ; 365.564,333.139 ccw(c366.068,333.628) v1(366.068,332.926) ; 365.573,293.238 cw(c366.093,292.72) 366.093,293.454 ; 365.573,293.671 ccw(c366.093,294.189) 366.093,293.454 ; 365.643,-145.598 ccw(c365.965,-145.276) 365.965,-145.731 ; 365.699,-145.654 cw(c365.316,-146.037) 365.858,-146.037 ; 365.74,-145.695 365.232,-145.187 364.47,-145.187 364.272,-144.989 364.272,-143.921 364.272,-142.337 365.088,-141.521 366.672,-141.521 366.104,-141.521 ; v1@365.841,334.477 ccw(c365.414,334.051) 365.414,334.654 ccw(c365.414,335.258) v1@365.841,334.831 ; v1@365.891,332.749 ccw(c365.464,332.323) 365.464,332.926 ccw(c365.464,333.53) v1@365.891,333.103 ; 366.145,282.672 ccw(c365.718,283.099) 366.322,283.099 ccw(c366.925,283.099) 366.499,282.672 ; 366.15,342.678 cw(c366.15,341.08) 367.28,342.21 cw(c368.41,343.34) 366.812,343.34 ; 366.15,342.878 cw(c366.15,341.763) 366.938,342.551 cw(c367.727,343.34) 366.612,343.34 ; 366.15,343.34 367.431,342.059 367.431,338.271 367.704,337.998 371.114,337.998 371.452,337.66 371.452,336.79 371.749,336.493 384.957,336.493 385.338,336.112 385.338,323.031 385.846,322.523 385.846,322.079 ; 366.322,281.745 366.322,284.666 366.976,285.32 372.183,285.32 372.901,286.038 372.901,292.674 ; v1@366.379,-133.122 ccw(c365.776,-133.122) 366.202,-132.695 ccw(c366.629,-132.268) v1@366.629,-132.872 ; v1@366.415,355.035 369.463,355.035 370.079,355.035 370.333,355.289 370.333,363.811 370.987,364.465 372.932,364.465 ; v1@366.542,295.574 368.001,295.574 ; 366.613,-153.924 ccw(c366.186,-153.497) 366.79,-153.497 ccw(c367.394,-153.497) 366.967,-153.924 ; 366.672,-139.521 369.622,-139.521 371.045,-140.944 371.362,-140.944 371.426,-140.944 372.124,-140.245 375.045,-140.245 375.37,-140.57 ; 366.672,-139.021 371.09,-139.021 ; 366.672,-138.521 370.731,-138.521 372.782,-136.471 372.782,-132.018 373.515,-131.285 ; 366.672,-138.021 370.666,-138.021 372.382,-136.305 372.382,-130.074 372.763,-129.693 374.63,-129.693 374.903,-129.42 374.903,-121.311 375.157,-121.057 379.71,-121.057 380.103,-120.665 380.103,-118.864 ; 366.672,-137.521 370.6,-137.521 371.982,-136.139 371.982,-129.82 372.509,-129.293 374.249,-129.293 374.503,-129.039 374.503,-117.755 375.045,-117.213 ; 366.672,-137.021 370.534,-137.021 371.582,-135.974 371.582,-129.185 371.874,-128.893 373.741,-128.893 374.103,-128.531 374.103,-117.139 374.884,-116.358 v1(374.884,-116.104) ; 366.672,-136.521 370.469,-136.521 371.182,-135.808 371.182,-128.95 371.816,-128.316 371.816,-125.031 ; 366.672,-135.521 368.46,-135.521 368.701,-135.281 368.701,-133.992 369.407,-133.286 ; 366.672,-135.021 367.905,-135.021 368.301,-134.626 368.301,-126.285 368.282,-126.266 368.282,-121.908 368.859,-121.33 372.706,-121.33 373.595,-120.441 373.595,-116.059 373.614,-116.04 ; 366.672,-134.521 367.481,-134.521 367.776,-134.227 367.776,-133.513 367.772,-133.509 367.772,-121.565 368.534,-120.803 371.836,-120.803 372.217,-120.422 372.217,-116.04 ; 366.672,-134.021 366.988,-134.021 367.368,-133.641 ; v1(366.923,354.273) 367.177,354.527 369.209,354.527 370.479,354.527 370.733,354.781 370.733,355.416 370.733,362.02 371.178,362.465 372.932,362.465 ; 367.018,294.932 cw(c367.336,294.614) 367.336,295.064 ; 367.071,294.986 cw(c367.275,294.782) 367.334,295.064 ; 367.337,-134.511 ccw(c367.337,-134.139) 367.6,-134.402 ; 367.345,-134.015 cw(c367.568,-133.841) 367.368,-133.641 ; 367.415,282.672 ccw(c366.988,283.099) 367.592,283.099 ccw(c368.195,283.099) 367.769,282.672 ; v1@367.558,353.638 370.098,353.638 370.987,353.638 371.241,353.892 371.241,356.211 371.495,356.465 ; 367.592,281.745 367.592,284.412 368.1,284.92 372.672,284.92 373.401,285.649 373.401,292.674 ; v1@367.735,353.462 cw(c368.161,353.035) 368.161,353.638 cw(c368.161,354.242) v1@367.735,353.815 ; 367.883,-153.924 ccw(c367.456,-153.497) 368.06,-153.497 ccw(c368.664,-153.497) 368.237,-153.924 ; 368.001,295.074 367.159,295.074 366.449,294.363 366.449,293.81 366.093,293.454 ; 368.001,296.074 377.396,296.074 377.684,296.361 377.684,303.185 378.622,304.123 379.608,304.123 v1(380.258,303.473) ; 368.001,296.574 363.528,296.574 ; 368.001,297.074 356.84,297.074 356.543,296.776 356.543,294.202 ; 368.001,301.074 364.646,301.074 363.932,301.788 363.932,302.578 363.93,302.58 363.93,304.113 363.932,304.115 363.932,325.385 363.745,325.571 355.65,325.571 355.635,325.556 354.619,325.556 354.35,325.825 ; 368.001,302.074 365.043,302.074 364.732,302.385 364.732,302.91 364.73,302.912 364.73,303.781 364.732,303.783 364.732,326.274 364.036,326.97 352.259,326.97 351.71,327.519 351.71,346.68 352.191,347.161 387.751,347.161 388.259,347.669 388.259,355.797 388.927,356.465 390.632,356.465 ; 368.001,302.574 365.409,302.574 365.132,302.851 365.132,303.075 365.13,303.077 365.13,303.616 365.132,303.618 365.132,326.782 364.544,327.37 352.424,327.37 352.11,327.685 352.11,345.175 ; 368.222,340.332 cw(c367.092,339.202) 368.69,339.202 cw(c370.288,339.202) 369.158,340.332 ; 368.363,340.473 cw(c367.574,339.685) 368.69,339.685 cw(c369.805,339.685) 369.016,340.473 ; 368.511,331.058 cw(c367.988,330.535) 368.728,330.535 cw(c369.468,330.535) 368.945,331.058 ; 368.544,306.624 cw(c368.02,306.101) 368.76,306.101 cw(c369.5,306.101) 368.977,306.624 ; 368.685,282.672 ccw(c368.258,283.099) 368.862,283.099 ccw(c369.465,283.099) 369.039,282.672 ; 368.69,340.8 368.69,338.664 368.955,338.398 371.374,338.398 371.856,337.916 371.856,337.167 372.13,336.893 385.319,336.893 385.738,336.474 385.738,335.731 385.738,323.393 385.973,323.158 386.862,323.158 387.243,322.777 387.243,322.079 ; 368.69,342.678 cw(c368.69,341.08) 369.82,342.21 cw(c370.95,343.34) 369.352,343.34 ; 368.69,342.878 cw(c368.69,341.763) 369.478,342.551 cw(c370.267,343.34) 369.152,343.34 ; 368.69,343.34 369.844,342.186 369.844,339.052 370.098,338.798 371.54,338.798 371.94,338.398 378.499,338.398 ; 368.728,331.275 368.728,330.297 368.332,329.901 368.332,313.379 368.332,313.335 368.701,312.966 374.448,312.966 375.401,312.014 375.401,304.974 ; 368.728,332.926 369.072,332.926 368.735,332.926 ; 368.76,306.841 368.76,306.081 369.082,305.759 370.225,305.759 ; 368.819,-133.874 cw(c369.407,-134.462) 369.407,-133.63 ; 368.862,281.745 368.862,283.777 369.497,284.412 372.926,284.412 373.901,285.387 373.901,292.674 ; 368.911,-133.782 ccw(c368.453,-133.324) 369.101,-133.324 ; 368.953,322.325 ccw(c368.407,322.871) 369.179,322.871 ; 368.963,323.635 cw(c368.44,323.112) 369.179,323.112 cw(c369.919,323.112) 369.396,323.635 ; 369.179,322.156 369.179,323.852 ; 369.179,322.826 ccw(c369.887,322.826) 369.386,322.325 ; 369.19,-135.192 cw(c368.974,-135.408) 369.28,-135.408 cw(c369.69,-135.407) 369.465,-135.064 ; 369.28,-135.777 cw(c369.933,-135.777) 369.575,-135.231 ; 369.792,-123.38 371.816,-123.38 ; 370.059,-139.021 cw(c370.059,-140.558) 371.145,-139.471 ; 370.086,305.759 cw(c370.086,305.324) 370.394,305.632 ; 370.143,-123.631 cw(c370.747,-124.235) 370.747,-123.38 ; 370.143,-123.157 ccw(c370.682,-122.617) 370.682,-123.38 ; 370.232,-140.131 ccw(c371.362,-139.001) 371.362,-140.599 ccw(c371.362,-139.614) 372.059,-140.311 ; 370.284,-123.772 cw(c371.229,-124.718) 371.229,-123.38 ; 370.284,-123.015 ccw(c371.165,-122.134) 371.165,-123.38 ; 370.289,305.695 ccw(c370.401,305.807) 370.401,305.649 ; 370.391,305.636 ccw(c370.225,305.586) 370.225,305.759 ; 370.401,292.674 370.401,294.632 370.733,294.964 377.464,294.964 378.084,295.584 378.084,302.95 378.607,303.473 v1(379.242,303.473) ; 370.401,304.974 370.401,305.584 370.225,305.759 ; 370.41,-111.278 370.727,-111.595 ; 370.411,306.841 370.901,306.351 370.901,304.974 ; 370.461,306.535 cw(c370.484,305.973) 370.882,306.371 cw(c371.215,306.704) 370.751,306.787 ; 370.542,-139.021 cw(c370.542,-140.075) 371.287,-139.33 ; 370.573,-140.473 ccw(c371.362,-139.684) 371.362,-140.799 ccw(c371.362,-140.297) 371.717,-140.652 ; 370.614,320.122 cw(c370.091,319.599) 370.83,319.599 cw(c371.57,319.599) 371.047,320.122 ; 370.83,320.338 370.83,316.353 370.83,313.777 371.228,313.379 375.559,313.379 375.901,313.038 375.901,304.974 ; 370.915,-140.814 ccw(c371.362,-140.367) 371.362,-140.999 ; 371.024,-139.021 cw(c371.024,-139.592) 371.428,-139.189 ; 371.23,340.8 371.23,339.68 371.495,339.414 375.051,339.414 376.575,340.938 378.499,340.938 ; 371.23,342.678 cw(c371.23,341.08) 372.36,342.21 cw(c373.49,343.34) 371.892,343.34 ; 371.23,342.878 cw(c371.23,341.763) 372.018,342.551 cw(c372.807,343.34) 371.692,343.34 ; 371.23,343.34 372.488,342.081 374.486,342.081 375.248,342.843 397.149,342.843 397.676,342.316 397.676,292.062 397.041,291.427 383.853,291.427 383.321,291.959 383.321,295.48 382.727,296.074 380.301,296.074 ; 371.6,-125.286 cw(c371.077,-125.809) 371.816,-125.809 cw(c372.556,-125.809) 372.033,-125.286 ; 371.6,-123.597 ccw(c371.077,-124.12) 371.077,-123.38 ccw(c371.077,-122.641) 371.6,-123.164 ; 371.668,-140.906 cw(c372.163,-140.906) 371.813,-140.556 ; 371.808,-113.663 cw(c371.069,-114.402) 372.111,-114.482 ; 372,-116.434 cw(c371.477,-116.957) 372.217,-116.957 cw(c372.957,-116.957) 372.434,-116.434 ; 372.116,-113.97 cw(c371.64,-114.446) 372.31,-114.497 ; 372.125,-114.198 ccw(c372.085,-114.072) 372.217,-114.072 ; 372.199,356.183 ccw(c371.516,355.5) 371.516,356.465 ; 372.199,356.748 cw(c371.516,357.431) 371.516,356.465 ; 372.199,362.183 ccw(c371.516,361.5) 371.516,362.465 ccw(c371.516,363.431) 372.199,362.748 ; 372.199,364.183 ccw(c371.516,363.5) 371.516,364.465 ccw(c371.516,365.431) 372.199,364.748 ; 372.217,-114.516 372.217,-114.072 ; 372.309,-114.198 cw(c372.349,-114.072) 372.217,-114.072 ; 372.519,317.469 cw(c371.996,316.946) 372.735,316.946 cw(c373.475,316.946) 372.952,317.469 ; 372.735,317.686 372.735,315.441 372.892,315.284 380.258,315.284 380.597,314.946 380.597,305.418 380.153,304.974 377.901,304.974 ; 372.782,-135.292 374.213,-135.292 ; 372.932,356.465 371.516,356.465 ; 373.397,-116.434 cw(c372.92,-116.912) 373.595,-116.912 ; 373.413,-114.258 ccw(c373.031,-113.818) 373.614,-113.818 ; 373.595,-117.002 cw(c374.399,-117.002) 373.831,-116.434 ; 373.614,-114.516 373.614,-113.818 ; 373.77,343.34 397.668,343.34 398.076,342.932 398.076,291.827 397.276,291.027 383.687,291.027 382.832,291.883 382.832,295.207 382.465,295.574 380.301,295.574 ; 373.815,-114.258 cw(c374.197,-113.818) 373.614,-113.818 ; 373.942,340.972 373.77,340.8 375.413,342.443 396.787,342.443 397.276,341.954 397.276,292.228 396.875,291.827 384.018,291.827 383.721,292.125 383.721,295.842 382.989,296.574 380.301,296.574 ; 373.958,-135.509 ccw(c373.435,-136.032) 373.435,-135.292 ccw(c373.435,-134.553) 373.958,-135.076 ; 374.096,343.013 cw(c374.885,342.225) 374.885,343.34 cw(c374.885,344.455) 374.096,343.667 ; 374.238,342.872 cw(c375.368,341.742) 375.368,343.34 cw(c375.368,344.938) 374.238,343.808 ; 374.386,326.83 374.411,326.806 ; 374.401,292.674 374.401,284.947 375.216,284.131 376.381,284.131 376.609,283.904 376.609,281.745 ; 374.408,322.172 374.577,322.004 ; 374.408,323.792 374.411,323.794 ; 374.583,-117.675 cw(c375.358,-118.45) 375.449,-117.358 ; 374.888,-117.37 cw(c375.405,-117.886) 375.465,-117.158 ; 374.901,292.674 374.901,285.209 375.578,284.531 377.505,284.531 377.879,284.158 377.879,281.745 ; 375.164,-117.302 ccw(c375.045,-117.338) 375.045,-117.213 ; 375.164,-117.125 cw(c375.045,-117.089) 375.045,-117.213 ; 375.191,-140.837 ccw(c375.082,-140.57) 375.37,-140.57 ; v1@375.287,-119.97 cw(c374.925,-120.36) 375.457,-120.36 ; 375.37,-141.402 375.37,-140.57 ; 375.401,292.674 375.401,285.598 376.067,284.931 378.883,284.931 379.149,284.666 379.149,281.745 ; v1(375.457,-119.787) 375.457,-120.36 ; 375.457,-117.213 375.045,-117.213 ; 375.549,-140.837 cw(c375.658,-140.57) 375.37,-140.57 ; v1@375.627,-119.97 ccw(c375.989,-120.36) 375.457,-120.36 ; 375.901,292.674 375.901,289.238 376.482,288.657 376.482,288.286 ; 375.902,-135.254 375.864,-135.292 377.649,-135.292 ; 375.902,-133.648 375.902,-133.521 ; 376.027,-88.366 cw(c378.789,-88.366) 376.836,-86.413 ; 376.027,-87.883 cw(c378.306,-87.883) 376.695,-86.271 ; 376.027,-87.4 cw(c377.823,-87.4) 376.553,-86.13 ; 376.027,-86.917 cw(c377.34,-86.917) 376.412,-85.989 ; 376.071,289.067 cw(c375.338,288.334) 376.375,288.325 ; 376.118,-135.509 cw(c376.641,-136.032) 376.641,-135.292 cw(c376.641,-134.553) 376.118,-135.076 ; v1@376.131,314.346 cw(c375.48,313.695) 376.401,313.695 ; 376.159,-86.201 cw(c375.661,-86.29) 376.019,-86.648 cw(c376.357,-86.986) 376.464,-86.52 ; 376.204,-84.326 ccw(c375.87,-84.513) 375.87,-84.13 ; 376.204,-83.934 cw(c375.87,-83.747) 375.87,-84.13 ; 376.27,-82.413 ccw(c375.587,-83.096) 375.587,-82.13 ccw(c375.587,-81.164) 376.27,-81.847 ; 376.27,-80.413 ccw(c375.587,-81.096) 375.587,-80.13 ccw(c375.587,-79.164) 376.27,-79.847 ; v1@376.273,314.487 cw(c375.963,314.178) 376.401,314.178 ; 376.401,292.674 376.401,289.446 376.736,289.111 377.498,289.111 377.752,288.857 377.752,285.739 378.006,285.485 380.108,285.485 380.419,285.174 380.419,281.745 ; 376.401,304.974 v1@376.401,314.43 ; 376.401,314.143 cw(c376.687,314.143) v1@376.485,314.346 ; 376.401,319.845 376.401,319.955 ; 376.409,288.73 cw(c376.006,288.328) 376.575,288.323 ; 376.432,282.672 ccw(c376.005,283.099) 376.609,283.099 ccw(c377.212,283.099) 376.786,282.672 ; 376.901,292.674 376.901,289.727 377.117,289.511 377.663,289.511 378.152,289.023 378.152,286.12 378.387,285.885 381.232,285.885 381.689,285.428 381.689,281.745 ; 376.901,306.193 cw(c378.768,306.193) 377.448,307.513 ; 376.901,306.676 cw(c378.285,306.676) 377.306,307.655 ; 376.901,306.955 376.901,304.974 376.901,307.717 ; 376.901,307.159 cw(c377.803,307.159) 377.165,307.796 ; 377.003,-84.13 375.87,-84.13 ; 377.003,-82.13 375.584,-82.13 375.138,-82.576 375.138,-89.307 374.503,-89.942 338.943,-89.942 338.481,-90.404 338.481,-91.42 ; 377.392,291.146 cw(c376.804,290.558) 377.636,290.558 ; 377.394,-135.509 ccw(c376.871,-136.032) 376.871,-135.292 ccw(c376.871,-134.553) 377.394,-135.076 ; 377.401,304.974 377.401,306.54 377.625,306.764 378.768,306.764 378.92,306.916 378.92,307.73 ; 377.484,291.054 ccw(c377.942,291.512) 377.942,290.864 ; 377.683,-133.757 377.683,-133.698 377.683,-133.571 ; 377.702,282.672 ccw(c377.275,283.099) 377.879,283.099 ccw(c378.482,283.099) 378.056,282.672 ; 377.98,290.558 377.401,291.138 377.401,292.674 377.401,294.324 378.734,295.657 v1(378.734,297.504) 378.734,300.298 379.009,300.574 380.301,300.574 382.655,300.574 382.909,300.828 382.909,301.659 383.036,301.659 ; 377.98,317.469 cw(c377.457,316.946) 378.196,316.946 cw(c378.936,316.946) 378.413,317.469 ; 378.04,337.939 ccw(c376.93,336.829) 376.93,338.398 ccw(c376.93,339.968) 378.04,338.858 ; 378.04,340.479 ccw(c376.93,339.369) 376.93,340.938 ccw(c376.93,342.508) 378.04,341.398 ; 378.181,338.08 ccw(c377.413,337.312) 377.413,338.398 ccw(c377.413,339.485) 378.181,338.717 ; 378.181,340.62 ccw(c377.413,339.852) 377.413,340.938 ccw(c377.413,342.025) 378.181,341.257 ; 378.196,317.686 378.196,315.949 378.461,315.684 380.639,315.684 380.997,315.327 380.997,302.954 ; 378.337,-119.119 cw(c377.814,-119.642) 378.554,-119.642 cw(c379.294,-119.642) 378.771,-119.119 ; 378.554,-118.864 378.554,-120.181 378.186,-120.549 375.646,-120.549 375.457,-120.36 ; v1@378.557,297.328 cw(c378.13,296.901) 378.734,296.901 cw(c379.337,296.901) v1@378.911,297.328 ; v1@378.557,297.681 ccw(c378.13,298.108) 378.734,298.108 ccw(c379.337,298.108) v1@378.911,297.681 ; 378.704,307.513 cw(c378.18,306.99) 378.92,306.99 cw(c379.66,306.99) 379.137,307.513 ; 378.972,282.672 ccw(c378.545,283.099) 379.149,283.099 ccw(c379.752,283.099) 379.326,282.672 ; 378.987,291.283 cw(c378.262,290.558) 379.287,290.558 ; v1@379.065,303.297 ccw(c378.638,302.87) 378.638,303.473 ccw(c378.638,304.077) v1@379.065,303.65 ; 379.272,290.998 ccw(c379.593,291.319) 379.593,290.864 ; 379.328,290.941 cw(c378.945,290.558) 379.487,290.558 ; 379.369,290.9 378.861,291.408 378.099,291.408 377.901,291.607 377.901,292.674 377.901,294.258 378.716,295.074 380.301,295.074 379.732,295.074 ; 379.886,-119.119 cw(c379.363,-119.642) 380.103,-119.642 cw(c380.842,-119.642) 380.319,-119.119 ; v1@380.008,303.473 ccw(c379.404,303.473) 379.831,303.9 ccw(c380.258,304.327) v1@380.258,303.723 ; 380.242,282.672 ccw(c379.815,283.099) 380.419,283.099 ccw(c381.022,283.099) 380.596,282.672 ; 380.301,297.074 383.251,297.074 384.673,295.652 384.991,295.652 385.054,295.652 385.753,296.35 388.674,296.35 388.999,296.025 ; 380.301,297.574 384.719,297.574 ; 380.301,298.074 384.36,298.074 386.411,300.125 386.411,304.577 387.144,305.31 ; 380.301,298.574 384.295,298.574 386.011,300.29 386.011,306.521 386.392,306.902 388.259,306.902 388.532,307.175 388.532,315.284 388.786,315.538 393.339,315.538 393.731,315.931 393.731,317.731 ; 380.301,299.074 384.229,299.074 385.611,300.456 385.611,306.775 386.138,307.302 387.878,307.302 388.132,307.556 388.132,318.84 388.673,319.382 ; 380.301,299.574 384.163,299.574 385.211,300.622 385.211,307.41 385.503,307.702 387.37,307.702 387.732,308.064 387.732,319.456 388.513,320.237 v1(388.513,320.491) ; 380.301,300.074 384.097,300.074 384.811,300.787 384.811,307.645 385.445,308.28 385.445,311.564 ; 380.301,301.074 382.089,301.074 382.329,301.314 382.329,302.603 383.036,303.31 ; 380.301,301.574 381.533,301.574 381.929,301.97 381.929,310.311 381.911,310.329 381.911,314.688 382.488,315.265 386.335,315.265 387.224,316.155 387.224,320.536 387.243,320.555 ; 380.301,302.074 381.11,302.074 381.405,302.369 381.405,303.083 381.401,303.087 381.401,315.03 382.163,315.792 385.465,315.792 385.846,316.173 385.846,320.555 ; 380.301,302.574 380.617,302.574 380.997,302.954 ; 380.929,-133.345 ccw(c380.076,-132.491) 381.283,-132.491 ccw(c382.49,-132.491) 381.637,-133.345 ; 380.966,302.084 ccw(c380.966,302.456) 381.229,302.193 ; 380.974,302.58 cw(c381.197,302.754) 380.997,302.954 ; 381.029,-131.644 cw(c380.416,-132.258) 381.283,-132.258 ; 381.071,-133.486 ccw(c380.559,-132.974) 381.283,-132.974 ccw(c382.007,-132.974) 381.495,-133.486 ; 381.283,-133.571 381.283,-131.517 ; 381.283,-133.378 cw(c383.735,-133.378) 382.001,-131.644 ; 381.283,-132.895 cw(c383.252,-132.895) 381.86,-131.503 ; 381.283,-132.412 cw(c382.769,-132.412) 381.718,-131.362 ; 381.283,-131.93 cw(c382.286,-131.93) 381.577,-131.22 ; 381.413,-71.827 381.554,-71.967 381.579,-71.942 ; 381.512,282.672 ccw(c381.085,283.099) 381.689,283.099 ccw(c382.292,283.099) 381.866,282.672 ; v1@382.417,-74.482 v1@382.631,-74.482 ; 382.448,302.722 cw(c383.036,302.133) 383.036,302.965 ; 382.54,302.814 ccw(c382.082,303.272) 382.729,303.272 ; 382.819,301.404 cw(c382.603,301.187) 382.909,301.187 ; 382.909,300.818 cw(c383.562,300.818) 383.204,301.364 ; 382.909,301.188 cw(c383.319,301.188) 383.094,301.532 ; 383.421,313.215 385.445,313.215 ; 383.688,297.574 cw(c383.688,296.037) 384.774,297.124 ; 383.771,312.965 cw(c384.375,312.361) 384.375,313.215 ; 383.771,313.439 ccw(c384.311,313.978) 384.311,313.215 ; 383.861,296.464 ccw(c384.991,297.594) 384.991,295.996 ccw(c384.991,296.981) 385.687,296.285 ; 383.913,312.823 cw(c384.858,311.878) 384.858,313.215 ; 383.913,313.58 ccw(c384.794,314.461) 384.794,313.215 ; 384.038,325.317 384.356,325 ; 384.17,297.574 cw(c384.17,296.52) 384.916,297.265 ; 384.202,296.123 ccw(c384.991,296.911) 384.991,295.796 ccw(c384.991,296.298) 385.346,295.943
